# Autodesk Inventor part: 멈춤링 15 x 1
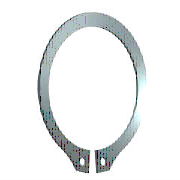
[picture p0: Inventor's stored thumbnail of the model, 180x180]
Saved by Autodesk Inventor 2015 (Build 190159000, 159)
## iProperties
IsCustomPart: 1
Created: 2012-02
Part Number: 멈춤링 15 x 1
Material: 강철, 연강
Description: 리테이닝 링(C형)
Document SubType Name: Modeling
Standard: KS B 1336
Designer: mduedu
Standards Organization: KS
Language: ko-KR
Size Designation: 15 x 1
Categories: <MemberInstance><Categories><Category DisplayName="샤프트 부품" InternalName="7f7aeb1f-a693-4053-b835-cee3144e0d98" Mnemonic="SHFT"><Category DisplayName="써클립" Inter
Density: 1 g/cm^3
Appearance: 파란색 - 벽 페인트 - 광택
Author: mduedu
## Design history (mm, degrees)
sketch "스케치1"
  geometry: L1 (-6, 0)-(6, 0) reference; L2 (0, 20.189)-(0, -80.536) reference; L3 (-48.09, 0)-(48.09, 0) reference; L4 (-0.425, -14.637)-(-0.425, -18.137); L5 (-0.425, -6.54)-(-0.425, -13.29); L6 (-2.795, 2.1)-(3.672, 2.1); L7 (0.425, -6.54)-(0.425, -13.29); L8 (0.425, -14.637)-(0.425, -18.137); C1 r 0.85 at (-1.7, -16.283); C2 r 0.85 at (1.7, -16.283); A1 r 7.15 centre (0, -7.5) between (0.425, -14.637) and (-0.425, -14.637); A2 r 9.075 centre (0, -6.975) between (4.291, -14.971) and (-4.291, -14.971); A3 r 10.646 centre (0, -7.5) between (-2.023, -17.952) and (-0.425, -18.137); A4 r 1.7 centre (-1.7, -16.283) between (-3.397, -16.376) and (-2.023, -17.952); A5 r 1.7 centre (-5.095, -16.469) between (-3.397, -16.376) and (-4.291, -14.971); A6 r 1.7 centre (5.095, -16.469) between (4.291, -14.971) and (3.397, -16.376); A7 r 1.7 centre (1.7, -16.283) between (2.023, -17.952) and (3.397, -16.376); A8 r 10.646 centre (0, -7.5) between (0.425, -18.137) and (2.023, -17.952)
  constraints: 16 point on circle, 12 end point, 10 centre point, 9 symmetric about line, 5 point on line, 4 tangent, 3 coincident, 2 horizontal, 1 perpendicular, 1 vertical, 5 other
  dimensions: "d0" = 14.3 diameter of A1 (= ND); "d1" = 3.5 distance of L4.end L4.start (= SRB2); "d6" = 0.425 distance between parallel lines of L2 L5 (= 0.25 x SD5); "d7" = 2.1 distance between parallel lines of L6 L3 (= SRB1); "d8" = 0.525 distance of A1.centre A2.centre (= 0.25 x SRB1); "d9" = 1.7 radius of A4 (= SD5); "d10" = 1.7 radius of A5 (= SD5); "d11" = 1.275 distance from line of L4 A4.centre (= 0.75 x SD5); "d12" = 1.7 diameter of C1 (= SD5); "d13" = 1.7 diameter of C2 (= SD5); "d14" = 7.5 distance from line of A1.centre L1 (= 0.5 x WD)
extrude "본체" new body sketch "스케치1" distance "d2" = 1 (= SD); taper "d3" = 0 deg
workaxis "Work Axis1"
workplane "Work Plane1"
body "Solid1"
other parameters: "WD" = 15 (= WDMIN) [user parameter; used in 1 equation term], "SD" = 1 [user parameter; used in 1 equation term], "SRB1" = 2.1 [user parameter; used in 2 equation terms], "ND" = 14.3 [user parameter; used in 1 equation term], "SRB2" = 3.5 [user parameter; used in 1 equation term], "SD5" = 1.7 [user parameter; used in 6 equation terms], "d15" = 0, "d16" = 0, "d17" = 0, "d41" = 0, "d42" = 0, "WDMIN" = 15 [user parameter; used in 1 equation term], "SD3" = 13.8 [user parameter], "WDMAX" = 16 [user parameter]
